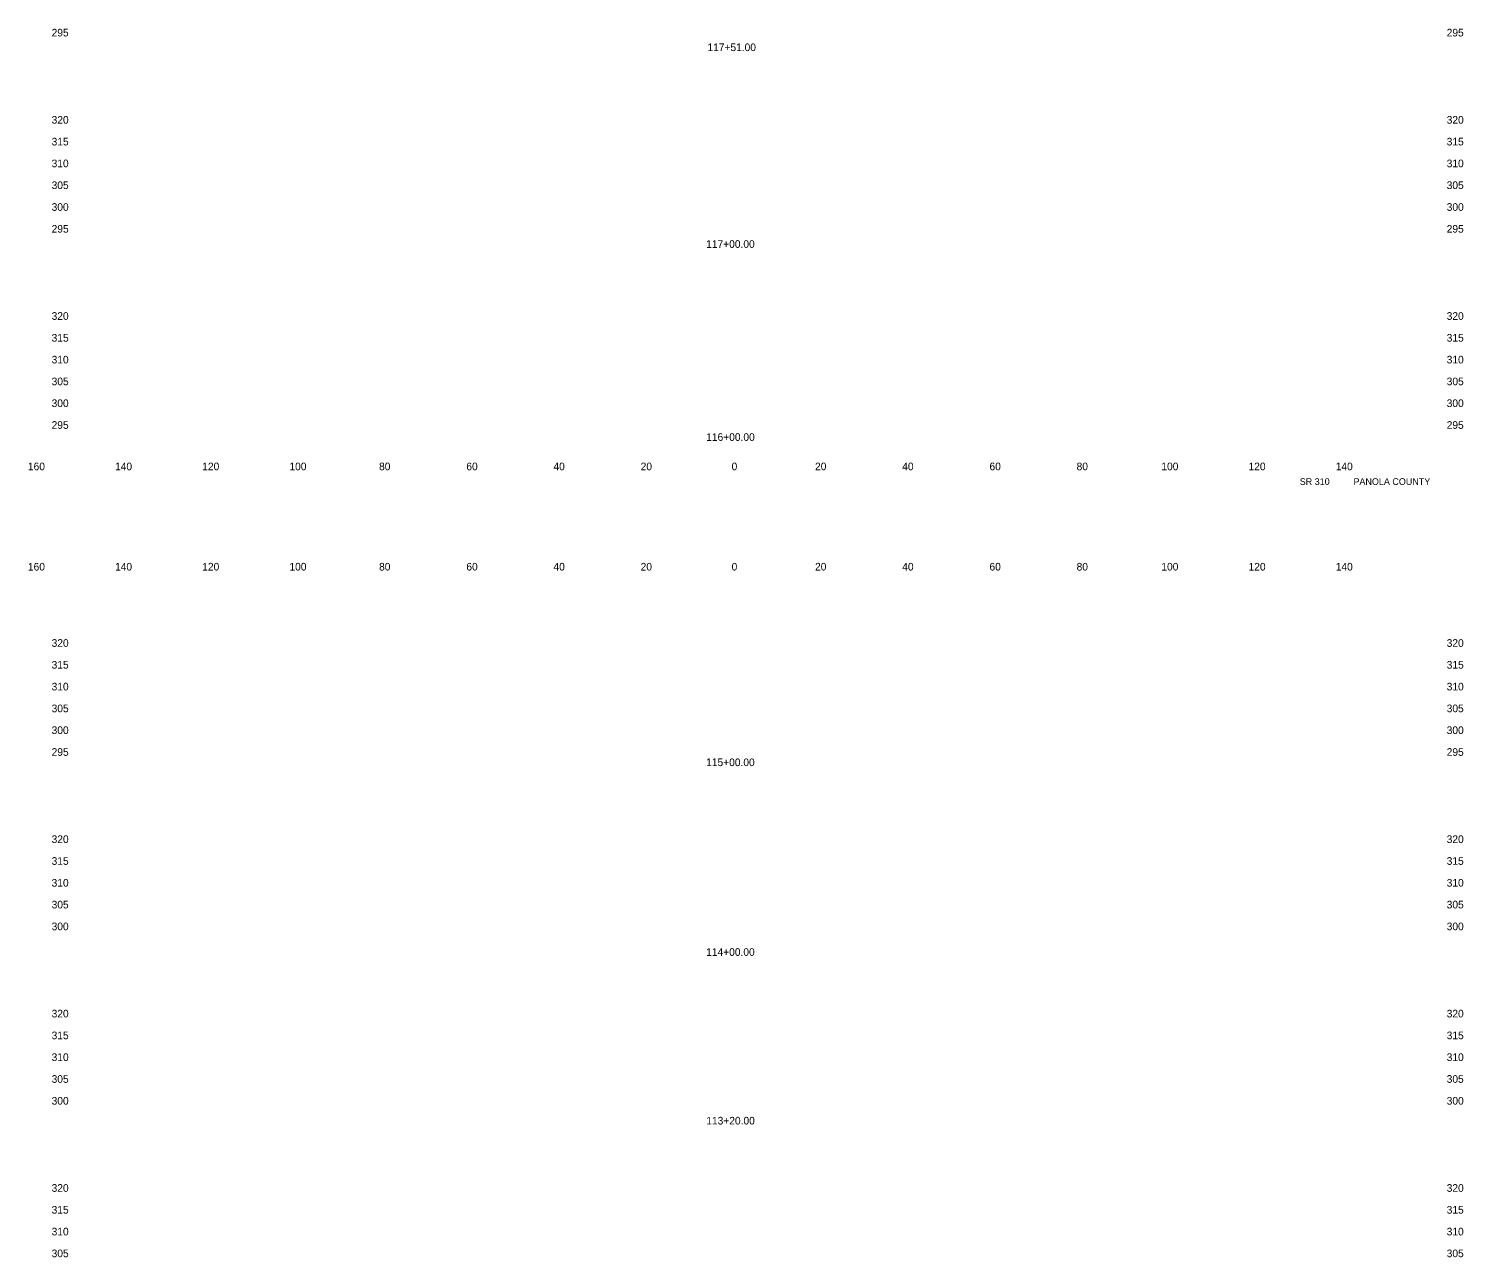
# Model space of a CAD drawing. Extents: x 21481 to 21810, y 6485 to 11067.
# Drawn here: x 21480.9 to 21809.9, y 7917.7 to 8199.5 of the extents above; entities that cross this region are included whole.
import ezdxf

# ---------------------------------------------------------------- set-up
doc = ezdxf.new("R2010")
doc.units = 0
for name, color, linetype in [('62', 7, 'Continuous'), ('XS_CELL', 7, 'Continuous'), ('XS_P_TX_DCH', 7, 'Continuous'), ('XS_P_TX_FS_BS', 7, 'Continuous')]:
    doc.layers.add(name, color=color, linetype=linetype)

msp = doc.modelspace()

# ---------------------------------------------------------------- texts
at = {"layer": '62'}
for s, p in [('  160  ', (21479.4, 8098.21)), ('  140  ', (21499.39, 8098.21)), ('  120  ', (21519.39, 8098.21)), ('  100  ', (21539.39, 8098.21)), ('  80  ', (21559.95, 8098.21)), ('  60  ', (21579.97, 8098.21)), ('  40  ', (21599.95, 8098.21)), ('  20  ', (21619.95, 8098.21)), ('  0  ', (21640.81, 8098.21)), ('  0  ', (21640.81, 8098.21)), ('  20  ', (21659.95, 8098.21)), ('  40  ', (21679.95, 8098.21)), ('  60  ', (21699.97, 8098.21)), ('  80  ', (21719.95, 8098.21)), ('  100  ', (21739.39, 8098.21)), ('  120  ', (21759.39, 8098.21)), ('  140  ', (21779.39, 8098.21)), ('  160  ', (21479.4, 8075.21)), ('  140  ', (21499.39, 8075.21)), ('  120  ', (21519.39, 8075.21)), ('  100  ', (21539.39, 8075.21)), ('  80  ', (21559.95, 8075.21)), ('  60  ', (21579.97, 8075.21)), ('  40  ', (21599.95, 8075.21)), ('  20  ', (21619.95, 8075.21)), ('  0  ', (21640.81, 8075.21)), ('  0  ', (21640.81, 8075.21)), ('  20  ', (21659.95, 8075.21)), ('  40  ', (21679.95, 8075.21)), ('  60  ', (21699.97, 8075.21)), ('  80  ', (21719.95, 8075.21)), ('  100  ', (21739.39, 8075.21)), ('  120  ', (21759.39, 8075.21)), ('  140  ', (21779.39, 8075.21))]:
    msp.add_text(s, height=1.75, dxfattribs=at).set_placement(p)
at = {"layer": 'XS_CELL'}
for s, p in [('  295  ', (21484.84, 8197.71)), ('  295  ', (21804.84, 8197.71)), ('  320  ', (21484.84, 8177.71)), ('  320  ', (21804.84, 8177.71)), ('  315  ', (21484.84, 8172.71)), ('  315  ', (21804.84, 8172.71)), ('  310  ', (21484.84, 8167.71)), ('  310  ', (21804.84, 8167.71)), ('  305  ', (21484.84, 8162.71)), ('  305  ', (21804.84, 8162.71)), ('  300  ', (21484.84, 8157.71)), ('  300  ', (21804.84, 8157.71)), ('  295  ', (21484.84, 8152.71)), ('  295  ', (21804.84, 8152.71)), ('  320  ', (21484.84, 8132.71)), ('  320  ', (21804.84, 8132.71)), ('  315  ', (21484.84, 8127.71)), ('  315  ', (21804.84, 8127.71)), ('  310  ', (21484.84, 8122.71)), ('  310  ', (21804.84, 8122.71)), ('  305  ', (21484.84, 8117.71)), ('  305  ', (21804.84, 8117.71)), ('  300  ', (21484.84, 8112.71)), ('  300  ', (21804.84, 8112.71)), ('  295  ', (21484.84, 8107.71)), ('  295  ', (21804.84, 8107.71)), ('  320  ', (21484.84, 8057.71)), ('  320  ', (21804.84, 8057.71)), ('  315  ', (21484.84, 8052.71)), ('  315  ', (21804.84, 8052.71)), ('  310  ', (21484.84, 8047.71)), ('  310  ', (21804.84, 8047.71)), ('  305  ', (21484.84, 8042.71)), ('  305  ', (21804.84, 8042.71)), ('  300  ', (21484.84, 8037.71)), ('  300  ', (21804.84, 8037.71)), ('  295  ', (21484.84, 8032.71)), ('  295  ', (21804.84, 8032.71)), ('  320  ', (21484.84, 8012.71)), ('  320  ', (21804.84, 8012.71)), ('  315  ', (21484.84, 8007.71)), ('  315  ', (21804.84, 8007.71)), ('  310  ', (21484.84, 8002.71)), ('  310  ', (21804.84, 8002.71)), ('  305  ', (21484.84, 7997.71)), ('  305  ', (21804.84, 7997.71)), ('  300  ', (21484.84, 7992.71)), ('  300  ', (21804.84, 7992.71)), ('  320  ', (21484.84, 7972.71)), ('  320  ', (21804.84, 7972.71)), ('  315  ', (21484.84, 7967.71)), ('  315  ', (21804.84, 7967.71)), ('  310  ', (21484.84, 7962.71)), ('  310  ', (21804.84, 7962.71)), ('  305  ', (21484.84, 7957.71)), ('  305  ', (21804.84, 7957.71)), ('  300  ', (21484.84, 7952.71)), ('  300  ', (21804.84, 7952.71)), ('  320  ', (21484.84, 7932.71)), ('  320  ', (21804.84, 7932.71)), ('  315  ', (21484.84, 7927.71)), ('  315  ', (21804.84, 7927.71)), ('  310  ', (21484.84, 7922.71)), ('  310  ', (21804.84, 7922.71)), ('  305  ', (21484.84, 7917.71)), ('  305  ', (21804.84, 7917.71))]:
    msp.add_text(s, height=1.75, dxfattribs=at).set_placement(p)
at = {"layer": 'XS_P_TX_DCH'}
for s, p in [('  117+51.00  ', (21635.27, 8194.35)), ('  117+00.00  ', (21634.98, 8149.22)), ('  116+00.00  ', (21634.99, 8104.95)), ('  115+00.00  ', (21634.98, 8030.35)), ('  114+00.00  ', (21634.98, 7986.83)), ('  113+20.00  ', (21635.01, 7948.15))]:
    msp.add_text(s, height=1.75, dxfattribs=at).set_placement(p)
at = {"layer": 'XS_P_TX_FS_BS'}
for s, p in [('SR 310', (21772.43, 8094.84)), ('SR 310', (21772.43, 8094.84)), ('SR 310', (21772.43, 8094.84)), ('PANOLA COUNTY', (21784.75, 8094.84)), ('PANOLA COUNTY', (21784.75, 8094.84)), ('PANOLA COUNTY', (21784.75, 8094.84))]:
    msp.add_text(s, height=1.54, dxfattribs=at).set_placement(p)

doc.saveas('drawing.dxf')
